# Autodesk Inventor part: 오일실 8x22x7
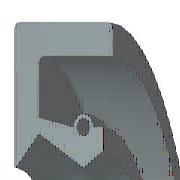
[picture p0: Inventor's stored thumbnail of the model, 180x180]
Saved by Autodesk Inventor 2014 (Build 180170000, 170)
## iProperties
IsCustomPart: 1
Company: 한국ATC센터
Created: 2014-07
Part Number: 오일실 8x22x7
Material: 고무
Description: 오일-실
Document SubType Name: Modeling
Standard: KS B 2804
Designer: KYOUNG IL JANG
Standards Organization: KS
Language: ko-KR
Size Designation: D - 8 22 7
Categories: <MemberInstance><Categories><Category DisplayName="샤프트 부품" InternalName="7f7aeb1f-a693-4053-b835-cee3144e0d98" Mnemonic="SHFT"><Category DisplayName="실링" Intern
Density: 0.93 g/cm^3
Appearance: 고무 - 검은색 - 버전 1.1
Author: KYOUNG IL JANG
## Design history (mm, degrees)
revolve "본체" stored, may be unused: angle "d17" = 90 deg
revolve "스프링1" stored, may be unused: angle "d18" = 90 deg
body "Solid1"
sketch "스케치1"
  geometry: L1 (0, 11)-(7, 11); L2 (7, 9.25)-(1.75, 9.25); L3 (1.75, 5.75)-(4.9, 4); L4 (4.9, 4)-(0, 4); L5 (0, 0)-(9.586, 0) reference; L6 (4.9, 4)-(6.3, 4.875); L7 (0, 18)-(0, -3) reference; L8 (-1.941, 0)-(11.507, 0) reference; L9 (4.2, 6.1)-(1.75, 6.59); L10 (1.75, 6.59)-(1.75, 9.25); L11 (0, 11)-(0, 4.088); L12 (4.9, 4)-(0, 4); L13 (1.75, 5.75)-(0.152, 4.028); L14 (7, 11)-(7, 9.25); L15 (5.6, 6.1)-(6.3, 6.1); L16 (6.3, 6.1)-(6.3, 4.875); C1 r 0.455 at (4.9, 6.1); A1 r 0.7 centre (4.9, 6.1) between (5.6, 6.1) and (4.2, 6.1); A2 r 0.088 centre (0.088, 4.088) between (0, 4.088) and (0.152, 4.028); 1 further point
  constraints: 28 end point, 5 horizontal alignment, 5 point on line, 4 point on circle, 4 vertical alignment, 3 centre point, 3 tangent, 2 collinear, 2 horizontal, 2 perpendicular, 1 coincident, 1 parallel
  dimensions: "d0" = 22 diameter of L1 L5 (= SD2); "d1" = 1.75 distance of L1.end L2.start (= SD); "d2" = 0.91 diameter of C1 (= SPDI); "d3" = 1.4 diameter of A1 (= SPDA); "d4" = 8 diameter of L3.end L5 (= NND); "d5" = 11.5 diameter of L3.start L5 (= TKDM); "d7" = 13.18 diameter of L9.end L5 (= TKDM + 0.24 x SWDT); "d8" = 1.75 distance between parallel lines of L11 L10 (= SD); "d9" = 4.9 distance from line of L11 C1.centre (= SPDST); "d10" = 12.2 diameter of C1.centre L5 (= HLDM); "d11" = 0.0875 radius of A2 (= 0.25 x LAB); "d12" = 6.3 distance between parallel lines of L11 L16 (= SDI); "d13" = 9.75 diameter of L6.end L5 (= ABDM); "d14" = 7 distance from line of L11 L1.end (= SWDT)
fillet "모깎기1" dims "d6" = 0.3 (= RR)
other parameters: "SD2" = 22 [user parameter; used in 1 equation term], "SWDT" = 7 [user parameter; used in 2 equation terms], "RR" = 0.3 [user parameter; used in 1 equation term], "SD" = 1.75 [user parameter; used in 2 equation terms], "NND" = 8 [user parameter; used in 1 equation term], "SPDA" = 1.4 [user parameter; used in 1 equation term], "SPDI" = 0.91 [user parameter; used in 1 equation term], "TKDM" = 11.5 [user parameter; used in 2 equation terms], "HLDM" = 12.2 [user parameter; used in 1 equation term], "ABDM" = 9.75 [user parameter; used in 1 equation term], "SDI" = 6.3 [user parameter; used in 1 equation term], "SPDST" = 4.9 [user parameter; used in 1 equation term], "LAB" = 0.35 [user parameter; used in 1 equation term], "d15" = 0, "d16" = 0, "d19" = 0
